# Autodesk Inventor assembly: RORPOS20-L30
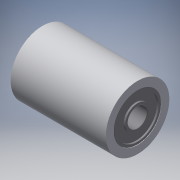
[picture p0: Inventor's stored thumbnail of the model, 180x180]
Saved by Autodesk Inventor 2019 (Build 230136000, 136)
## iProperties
Category: PARTsolutions
Company: MISUMI
Created: 2022-11
Part Number: RORPOS20-L30
Catalog Web Link: www.cadenas.de
Description: RORPOS, RORPHS, RORPES, RORPJS, RORPSS, RORPQS, RORMCS-Plastic Roller -Milled/Straight-
Vendor: MISUMI
Document SubType Name: Assembly
Designer: psAdmin
Manufacturer: MISUMI
Mass: 7.38247 g
Surface Area: 48.2474 cm^2
Volume: 7.38247 cm^3
Density: 1 g/cm^3
Title: RORPOS20-L30
Author: Cadenas PARTsolutions
Comments: Plastic Roller -Milled/Straight-
PSOL_IDENT_0: {$CADENAS_DATA/23d-libs/misumi/metric/53_rollers/rorpes_asmtab.prj},228 {VTYP=3D},{STYP=ASSTAB},{NB=
PSOL_IDENT_1: RORPOS20-L30},{LINA=RORPOS20-L30},{NN=RORPOS, RORPHS, RORPES, RORPJS, RORPSS, RORPQS, RORMCS},{DATE=
PSOL_IDENT_2: 30.06.2021 13:26:50},{GEOMDATE=18.05.2012},{VERSION=},{LINEID=10},{WBVAR=MAT,MATB,L},{WBNUMERIC=L}
PSOL_IDENT_3: {NB=RORPOS20-L30},{LINA=RORPOS20-L30},{KT=DUMMY},{PN=RORPOS20-L30},{TYPE=RORPOS},{MAT=1},{ALT1=},{MA
PSOL_IDENT_4: TB=S},{MATBALG= 'S', 'Steel', 'SS', 'Stainless Steel' },{MATB1=Steel},{MATB2=52100 Bearing Steel},{N
PSOL_IDENT_5: O=20},{NOM=20},{L=30},{L0=[15-100/1]},{BU=B696ZZx2},{BUN=696ZZ},{D=20},{D1=15},{DD=6},{B=5},{DDHH=10
PSOL_IDENT_6: },{PPATH=rorpos_asmtpl.prj}
NB: RORPOS20-L30
NN: RORPOS, RORPHS, RORPES, RORPJS, RORPSS, RORPQS, RORMCS
NT: Plastic Roller -Milled/Straight-
NBSYN: $PN.
LINA: RORPOS20-L30
CATALOG: Misumi
PN: RORPOS20-L30
MAT: Polyacetal
MATB: Steel
NO: 20
L: 30
BU: B696ZZx2
D: 20
D1: 15
DD: 6
B: 5
DDHH: 10
SUPPLIER: MISUMI
ARTICLENO: RORPOS20-L30
BOMINFO: RORPOS20-L30
CREATOR: CADENAS GmbH
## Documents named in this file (3)
- e:\temp\worker_COMMON_8\temp\tmp_3520_50_dCx11\format_0\RORPOS20-L30.iam
- e:\temp\worker_COMMON_8\temp\tmp_3520_50_dCx11\format_0\RORPOS20-L30_1.ipt
- e:\temp\worker_COMMON_8\temp\tmp_3520_50_dCx11\format_0\B696ZZ.ipt
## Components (3 placed, 2 different names)
1. RORPOS20-L30_1:1 — body_to_B_L__Z@1 <-> to_housing_Z@2, body_to_B_R__Z@1 <-> to_housing_Z@3
2. B696ZZ:1 — body_to_B_L__Z@1 <-> to_housing_Z@2
3. B696ZZ:2 — body_to_B_R__Z@1 <-> to_housing_Z@3
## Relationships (2: Mate 2)
- body_to_B_L__Z@1 <-> to_housing_Z@2 [Mate]: RORPOS20-L30_1:1 ↔ B696ZZ:1
- body_to_B_R__Z@1 <-> to_housing_Z@3 [Mate]: RORPOS20-L30_1:1 ↔ B696ZZ:2
